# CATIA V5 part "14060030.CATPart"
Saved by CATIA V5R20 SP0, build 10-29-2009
Part number: 14060030
Definition: NONE
Nomenclature: 14060030
Source: Unknown
Description: 14060030
Bounding box of the stored display mesh (mm): x -15 to 60, y -44 to 33.913, z -34.1 to 34.1
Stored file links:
  C:\Users\Utente\Desktop\IO LAVORO\3D X SITO CF\X SITO\PLASTICA\RF2\14060030.CATPart
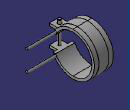
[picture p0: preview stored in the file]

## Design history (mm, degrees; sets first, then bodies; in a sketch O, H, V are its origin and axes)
Body1 "14060030" (main body)
  Solid1: solid without history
